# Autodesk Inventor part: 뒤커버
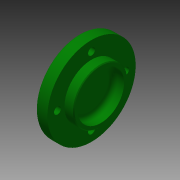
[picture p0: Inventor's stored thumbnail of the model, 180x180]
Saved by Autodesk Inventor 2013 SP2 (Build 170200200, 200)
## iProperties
Created: 2015-12
Part Number: 뒤커버
Material: 알루미늄 6061
Document SubType Name: Modeling
Designer: mduedu
Density: 2.71 g/cm^3
Author: mduedu
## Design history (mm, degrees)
sketch "스케치1"
  geometry: L1 (0, 0)-(14, 0); L2 (14, 0)-(14, 17.5); L3 (14, 17.5)-(8, 17.5); L4 (8, 17.5)-(8, 28.5); L5 (8, 28.5)-(0, 28.5); L6 (0, 28.5)-(0, 0)
  constraints: 12 end point, 4 parallel, 1 horizontal, 1 perpendicular
  dimensions: "d0" = 14 distance between parallel lines of L2 L6; "d2" = 8 distance of L4.end L5.end; "d3" = 57 diameter of L5 L1; "d4" = 35 diameter of L3 L1
revolve "회전1" sketch "스케치1" stored, may be unused: angle "d5" = 90 deg
hole "구멍1" diameter "d8" = 30; stored, may be unused: countersink angle "d12" = 90 deg, drill point angle "d14" = 0 deg; dims "d9" = 6, "d10" = 4, "d11" = 2, "d13" = 7, "d39" = 10, "d40" = 10
fillet "모깎기3" dims "d38" = 2
fillet "모깎기4" dims "d41" = 3
chamfer "모따기2" distance "d42" = 0.5; stored, may be unused: second distance "d43" = 2, angle "d44" = 45 deg
sketch "스케치2" dims "d45" = 42
  geometry: 6 further points
  constraints: 2 vertical alignment, 1 coincident, 7 other
  dimensions: "d48" = 360 deg dimension on point (0, 0) point (0, 21) (derived)
sketch "스케치3" dims "d57" = 44
  geometry: C1 r 26.5 at (0, 0) reference; 5 further points
  constraints: 1 coincident, 1 horizontal alignment, 2 other
hole "구멍4" sketch "스케치3" at (-22, 0), (0, -22), (22, 0), (0, 22) diameter "d50" = 4.5; stored, may be unused: countersink angle "d54" = 90 deg, drill point angle "d56" = 0 deg; dims "d51" = 6, "d52" = 8, "d53" = 4.6, "d55" = 8
node "솔리드1"
